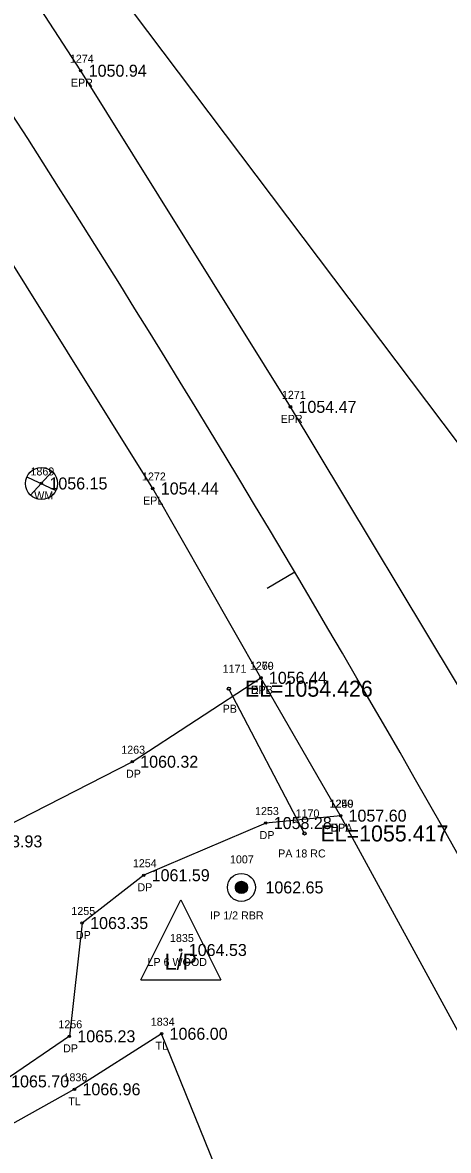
# Model space of a CAD drawing. Extents: x 1578957 to 1581675, y 1115963 to 1120391.
# Drawn here: x 1580275 to 1580328.3, y 1116727.6 to 1116868.5 of the extents above; entities that cross this region are included whole.
import ezdxf

# ---------------------------------------------------------------- set-up
doc = ezdxf.new("R2010")
doc.units = 0
for name, color, linetype in [('RD_EX_DR_Pipe', 7, 'Continuous'), ('RD_EX_DR_Pipe_txCode', 7, 'Continuous'), ('RD_EX_Driveway', 7, 'Continuous'), ('RD_EX_Driveway_txCode', 7, 'Continuous'), ('RD_EX_DV_Prop_txCode', 7, 'Continuous'), ('RD_EX_DV_PropPin', 7, 'Continuous'), ('RD_EX_Road', 7, 'Continuous'), ('RD_EX_Road_txCode', 7, 'Continuous'), ('RD_EX_TX_Driveway_ELEV', 7, 'Continuous'), ('RD_EX_TX_DV_Prop_ELEV', 7, 'Continuous'), ('RD_EX_TX_Road_ELEV', 7, 'Continuous'), ('RD_EX_TX_UT_ELEV', 7, 'Continuous'), ('RD_EX_TX_VEG_ELEV', 7, 'Continuous'), ('RD_EX_UT', 7, 'Continuous'), ('RD_EX_UT_txCode', 7, 'Continuous'), ('RD_EX_VEG', 7, 'Continuous'), ('RD_EX_VEG_txCode', 7, 'Continuous'), ('RD_HC_Cl', 7, 'Continuous'), ('RD_HC_Data_Tic', 7, 'Continuous'), ('RD_SMD_Locator', 7, 'Continuous'), ('RD_TX_Pipe_ElevEX', 7, 'Continuous')]:
    doc.layers.add(name, color=color, linetype=linetype)

msp = doc.modelspace()

# ---------------------------------------------------------------- linework, layer by layer
at = {"layer": 'RD_EX_DR_Pipe'}
msp.add_line((1580310.26, 1116767.24), (1580300.81, 1116785.32), dxfattribs=at)
at = {"layer": 'RD_EX_Driveway'}
for points in [[(1580246.78, 1116754.37), (1580269.24, 1116766.25), (1580288.73, 1116776.2), (1580304.81, 1116786.68)], [(1580314.77, 1116769.46), (1580305.42, 1116768.54), (1580290.16, 1116762.02), (1580282.47, 1116756.05), (1580280.87, 1116741.9), (1580272.59, 1116736.27), (1580265.92, 1116743.28), (1580263.29, 1116747.53), (1580252.24, 1116743.11)]]:
    msp.add_lwpolyline(points, dxfattribs=at)
at = {"layer": 'RD_EX_DV_PropPin'}
for p, q in [((1580301.64, 1116760.31), (1580301.64, 1116760.7)), ((1580301.68, 1116760.21), (1580301.68, 1116760.8)), ((1580301.71, 1116760.13), (1580301.71, 1116760.87)), ((1580301.75, 1116760.08), (1580301.75, 1116760.93)), ((1580301.78, 1116760.03), (1580301.78, 1116760.98)), ((1580301.82, 1116759.99), (1580301.82, 1116761.02)), ((1580301.85, 1116759.95), (1580301.85, 1116761.05)), ((1580301.89, 1116759.92), (1580301.89, 1116761.09)), ((1580301.92, 1116759.89), (1580301.92, 1116761.11)), ((1580301.96, 1116759.87), (1580301.96, 1116761.14)), ((1580301.99, 1116759.85), (1580301.99, 1116761.16)), ((1580302.03, 1116759.83), (1580302.03, 1116761.18)), ((1580302.06, 1116759.81), (1580302.06, 1116761.2)), ((1580302.1, 1116759.8), (1580302.1, 1116761.21)), ((1580302.13, 1116759.78), (1580302.13, 1116761.22)), ((1580302.17, 1116759.77), (1580302.17, 1116761.24)), ((1580302.2, 1116759.76), (1580302.2, 1116761.24)), ((1580302.24, 1116759.76), (1580302.24, 1116761.25)), ((1580302.27, 1116759.75), (1580302.27, 1116761.26)), ((1580302.31, 1116759.75), (1580302.31, 1116761.26)), ((1580302.34, 1116759.74), (1580302.34, 1116761.26)), ((1580302.38, 1116759.74), (1580302.38, 1116761.26)), ((1580302.41, 1116759.74), (1580302.41, 1116761.26)), ((1580302.45, 1116759.75), (1580302.45, 1116761.26)), ((1580302.48, 1116759.75), (1580302.48, 1116761.26)), ((1580302.52, 1116759.76), (1580302.52, 1116761.25)), ((1580302.55, 1116759.76), (1580302.55, 1116761.24)), ((1580302.59, 1116759.77), (1580302.59, 1116761.24)), ((1580302.62, 1116759.78), (1580302.62, 1116761.22)), ((1580302.66, 1116759.8), (1580302.66, 1116761.21)), ((1580302.69, 1116759.81), (1580302.69, 1116761.2)), ((1580302.73, 1116759.83), (1580302.73, 1116761.18)), ((1580302.76, 1116759.85), (1580302.76, 1116761.16)), ((1580302.8, 1116759.87), (1580302.8, 1116761.14)), ((1580302.83, 1116759.89), (1580302.83, 1116761.11)), ((1580302.87, 1116759.92), (1580302.87, 1116761.09)), ((1580302.9, 1116759.95), (1580302.9, 1116761.05)), ((1580302.94, 1116759.99), (1580302.94, 1116761.02)), ((1580302.98, 1116760.03), (1580302.98, 1116760.98)), ((1580303.01, 1116760.08), (1580303.01, 1116760.93)), ((1580303.05, 1116760.13), (1580303.05, 1116760.87)), ((1580303.08, 1116760.21), (1580303.08, 1116760.8)), ((1580303.12, 1116760.31), (1580303.12, 1116760.7))]:
    msp.add_line(p, q, dxfattribs=at)
for radius in [1.75, 0.761]:
    msp.add_circle((1580302.38, 1116760.5), radius, dxfattribs=at)
at = {"layer": 'RD_EX_Road'}
for points in [[(1580570.71, 1116498.67), (1580529.36, 1116480.65), (1580519.91, 1116479.43), (1580510.64, 1116479.83), (1580504.14, 1116481.67), (1580497.17, 1116485.13), (1580490.27, 1116490.58), (1580483.83, 1116498.29), (1580485.04, 1116499.02), (1580478.37, 1116510.01), (1580451.15, 1116557.41), (1580425.99, 1116599.55), (1580403.29, 1116644.83), (1580382.32, 1116688.41), (1580373.95, 1116705.15), (1580352.79, 1116744.5), (1580332.46, 1116780.72), (1580308.51, 1116820.53), (1580282.29, 1116862.52), (1580254.51, 1116905.2), (1580227.5, 1116946.75), (1580201.69, 1116988.26)], [(1580373.02, 1116418.01), (1580425.37, 1116439.24), (1580432.48, 1116444.21), (1580439.18, 1116451.49), (1580444.63, 1116463.6), (1580445.94, 1116475), (1580444.74, 1116484.46), (1580443.03, 1116489.18), (1580441.49, 1116488.99), (1580438.54, 1116496.4), (1580426.11, 1116533.96), (1580423.22, 1116543.6), (1580405.6, 1116590.01), (1580384.87, 1116635.19), (1580363.63, 1116679.91), (1580314.77, 1116769.46), (1580304.81, 1116786.68), (1580291.3, 1116810.33), (1580264.82, 1116852.68), (1580237.53, 1116894.27), (1580210.3, 1116936.03), (1580183.44, 1116978.21)]]:
    msp.add_lwpolyline(points, dxfattribs=at)
at = {"layer": 'RD_EX_UT'}
for p, q in [((1580276.03, 1116809.5), (1580278.7, 1116812.4)), ((1580275.55, 1116811.8), (1580279.18, 1116810.08)), ((1580289.8, 1116748.95), (1580294.8, 1116758.95)), ((1580294.8, 1116758.95), (1580299.8, 1116748.95)), ((1580289.8, 1116748.95), (1580299.8, 1116748.95))]:
    msp.add_line(p, q, dxfattribs=at)
msp.add_circle((1580277.38, 1116810.96), 2, dxfattribs=at)
at = {"layer": 'RD_EX_VEG'}
for points in [[(1580391.81, 1116828.04), (1580364.95, 1116813.73), (1580356.71, 1116779.91), (1580277, 1116885.57)], [(1580267.27, 1116691.72), (1580298.49, 1116705.2), (1580314.83, 1116697.51), (1580311.16, 1116695.92), (1580292.4, 1116742.22), (1580281.51, 1116735.28), (1580235.09, 1116709.4)]]:
    msp.add_lwpolyline(points, dxfattribs=at)
at = {"layer": 'RD_HC_Cl'}
msp.add_arc((1578700.89, 1115846.2), 1869.67, 25.90948, 32.94895, dxfattribs=at)
at = {"layer": 'RD_HC_Data_Tic'}
msp.add_line((1580309.04, 1116799.87), (1580305.6, 1116797.83), dxfattribs=at)
at = {"layer": 'RD_SMD_Locator'}
for centre, radius in [((1580282.29, 1116862.52), 0.15), ((1580308.51, 1116820.53), 0.15), ((1580277.38, 1116810.96), 0.15), ((1580291.3, 1116810.33), 0.15), ((1580304.81, 1116786.68), 0.15), ((1580304.81, 1116786.68), 0.15), ((1580300.81, 1116785.32), 0.2), ((1580288.73, 1116776.2), 0.15), ((1580305.42, 1116768.54), 0.15), ((1580314.77, 1116769.46), 0.15), ((1580314.77, 1116769.46), 0.15), ((1580310.26, 1116767.24), 0.2), ((1580290.16, 1116762.02), 0.15), ((1580302.38, 1116760.5), 0.15), ((1580282.47, 1116756.05), 0.15), ((1580294.8, 1116752.68), 0.15), ((1580280.87, 1116741.9), 0.15), ((1580292.4, 1116742.22), 0.15), ((1580281.51, 1116735.28), 0.15)]:
    msp.add_circle(centre, radius, dxfattribs=at)

# ---------------------------------------------------------------- texts
at = {"layer": 'RD_EX_DR_Pipe_txCode'}
for s, p in [('1171', (1580300.03, 1116787.32)), ('PB', (1580300.03, 1116782.32)), ('1170', (1580309.15, 1116769.24)), ('PA 18 RC', (1580306.97, 1116764.24))]:
    msp.add_text(s, height=1, dxfattribs=at).set_placement(p)
at = {"layer": 'RD_EX_Driveway_txCode'}
for s, p in [('1269', (1580303.44, 1116787.68)), ('DPB', (1580303.56, 1116784.68)), ('1263', (1580287.36, 1116777.2)), ('DP', (1580287.95, 1116774.2)), ('1253', (1580304.08, 1116769.54)), ('1250', (1580313.38, 1116770.46)), ('DP', (1580304.65, 1116766.54)), ('DPA', (1580313.5, 1116767.46)), ('1254', (1580288.81, 1116763.02)), ('DP', (1580289.38, 1116760.02)), ('1255', (1580281.12, 1116757.05)), ('DP', (1580281.69, 1116754.05)), ('1256', (1580279.5, 1116742.9)), ('DP', (1580280.09, 1116739.9))]:
    msp.add_text(s, height=1, dxfattribs=at).set_placement(p)
at = {"layer": 'RD_EX_DV_Prop_txCode'}
for s, p in [('1007', (1580300.95, 1116763.5)), ('IP 1/2 RBR', (1580298.47, 1116756.5))]:
    msp.add_text(s, height=1, dxfattribs=at).set_placement(p)
at = {"layer": 'RD_EX_Road_txCode'}
for s, p in [('1274', (1580280.94, 1116863.52)), ('EPR', (1580281.06, 1116860.52)), ('1271', (1580307.44, 1116821.53)), ('EPR', (1580307.28, 1116818.53)), ('1272', (1580289.95, 1116811.33)), ('EPL', (1580290.09, 1116808.33)), ('1270', (1580303.43, 1116787.68)), ('EPL', (1580303.61, 1116784.68)), ('1249', (1580313.42, 1116770.46)), ('EPL', (1580313.56, 1116767.46))]:
    msp.add_text(s, height=1, dxfattribs=at).set_placement(p)
at = {"layer": 'RD_EX_TX_Driveway_ELEV'}
for s, p in [('1056.44', (1580305.81, 1116785.93)), ('1060.32', (1580289.73, 1116775.45)), ('1057.60', (1580315.77, 1116768.71)), ('1058.28', (1580306.42, 1116767.79)), ('1063.93', (1580270.24, 1116765.5)), ('1061.59', (1580291.16, 1116761.27)), ('1063.35', (1580283.47, 1116755.3)), ('1065.23', (1580281.87, 1116741.15)), ('1065.70', (1580273.59, 1116735.52))]:
    msp.add_text(s, height=1.5, dxfattribs=at).set_placement(p)
at = {"layer": 'RD_EX_TX_DV_Prop_ELEV'}
msp.add_text('1062.65', height=1.5, dxfattribs=at).set_placement((1580305.38, 1116759.75))
at = {"layer": 'RD_EX_TX_Road_ELEV'}
for s, p in [('1050.94', (1580283.29, 1116861.77)), ('1054.47', (1580309.51, 1116819.78)), ('1054.44', (1580292.3, 1116809.58)), ('1056.44', (1580305.81, 1116785.93)), ('1057.60', (1580315.77, 1116768.71))]:
    msp.add_text(s, height=1.5, dxfattribs=at).set_placement(p)
at = {"layer": 'RD_EX_TX_UT_ELEV'}
for s, p in [('1056.15', (1580278.38, 1116810.21)), ('1064.53', (1580295.8, 1116751.93))]:
    msp.add_text(s, height=1.5, dxfattribs=at).set_placement(p)
at = {"layer": 'RD_EX_TX_VEG_ELEV'}
for s, p in [('1066.00', (1580293.4, 1116741.47)), ('1066.96', (1580282.51, 1116734.53))]:
    msp.add_text(s, height=1.5, dxfattribs=at).set_placement(p)
at = {"layer": 'RD_EX_UT'}
msp.add_text('L/P', height=2, dxfattribs=at).set_placement((1580292.79, 1116750.23))
at = {"layer": 'RD_EX_UT_txCode'}
for s, p in [('1869', (1580276.01, 1116811.96)), ('WM', (1580276.48, 1116808.96)), ('1835', (1580293.45, 1116753.68)), ('LP 6 WOOD', (1580290.64, 1116750.68))]:
    msp.add_text(s, height=1, dxfattribs=at).set_placement(p)
at = {"layer": 'RD_EX_VEG_txCode'}
for s, p in [('1834', (1580291.05, 1116743.22)), ('TL', (1580291.63, 1116740.22)), ('1836', (1580280.14, 1116736.28)), ('TL', (1580280.74, 1116733.28))]:
    msp.add_text(s, height=1, dxfattribs=at).set_placement(p)
at = {"layer": 'RD_TX_Pipe_ElevEX'}
for s, p in [('EL=1054.426', (1580302.81, 1116784.32)), ('EL=1055.417', (1580312.26, 1116766.24))]:
    msp.add_text(s, height=2, dxfattribs=at).set_placement(p)

doc.saveas('drawing.dxf')
